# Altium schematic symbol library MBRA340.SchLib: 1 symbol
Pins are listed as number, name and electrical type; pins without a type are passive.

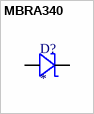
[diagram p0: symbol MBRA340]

## MBRA340
designator D?
DIODE, SCHOTTKY, 3A, 40V, SMA; MP: MBRA340; MF: ON Semiconductor
footprint MBRA340
pins: A, C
